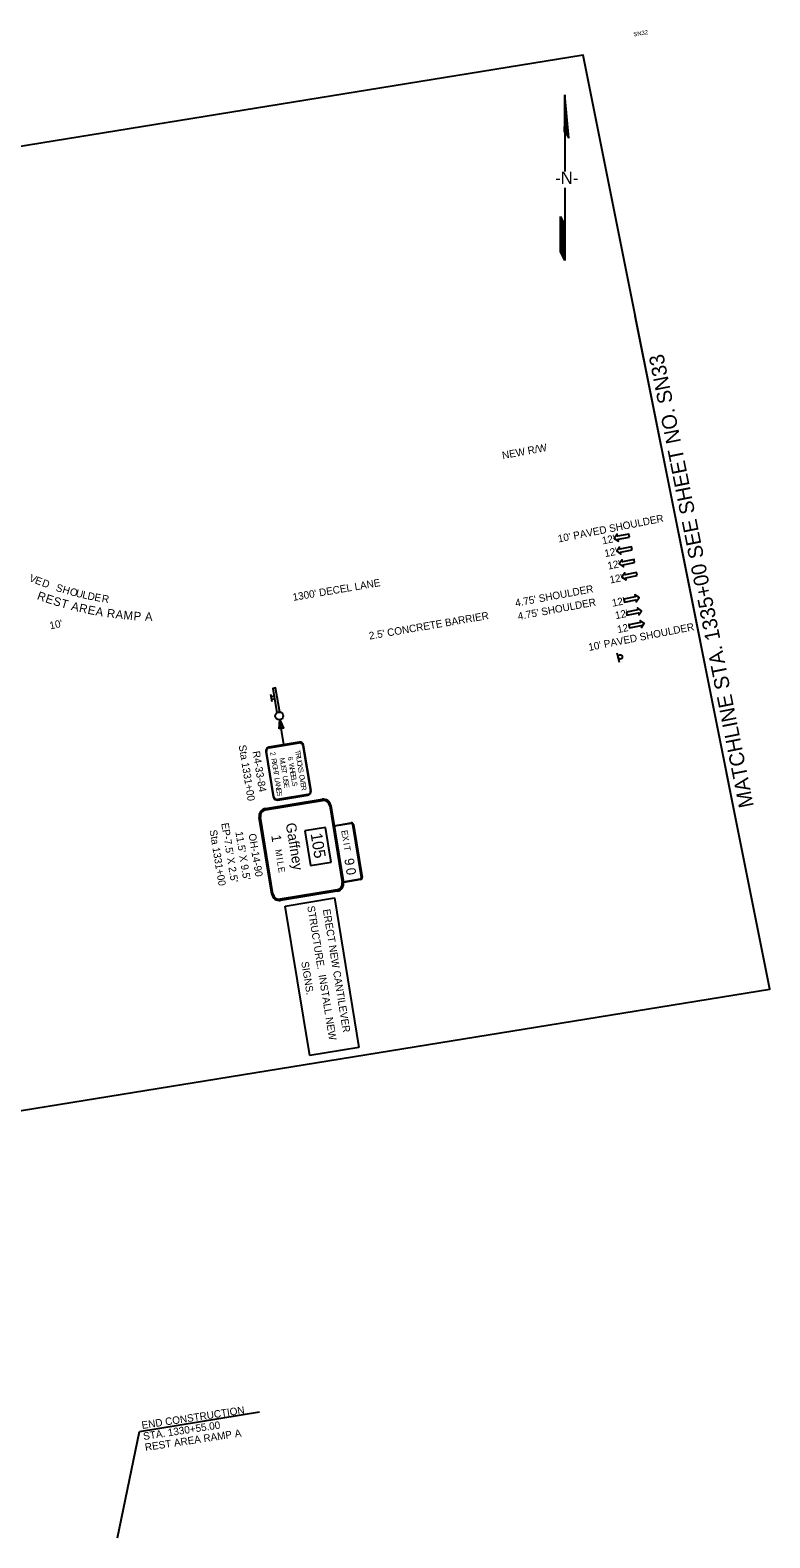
# Model space of a CAD drawing. Extents: x 1781216 to 1782851, y 1180019 to 1181557.
# Drawn here: x 1782155 to 1782851, y 1180139 to 1181557 of the extents above; entities that cross this region are included whole.
import ezdxf

# ---------------------------------------------------------------- set-up
doc = ezdxf.new("R2010")
doc.units = 0
for name, color, linetype in [('RD_HC_Data', 7, 'Continuous'), ('RD_PD_FOC', 7, 'Continuous'), ('RD_PD_GR', 7, 'Continuous'), ('RD_PD_PatLn1', 7, 'Continuous'), ('RD_PD_PaveShd', 7, 'Continuous'), ('RD_SHT_MatchLine', 7, 'Continuous'), ('RD_Sketch1', 7, 'Continuous'), ('RD_Sketch2', 7, 'Continuous'), ('RD_TX_RoadID', 7, 'Continuous')]:
    doc.layers.add(name, color=color, linetype=linetype)

# ---------------------------------------------------------------- blocks, each defined once
blk = doc.blocks.new('NA5')
at = {"layer": 'RD_Sketch1'}
for p, q in [((47.5, 65.9), (26.8, 37.4)), ((26.8, 30.6), (47.5, 65.9)), ((27.2, 37.5), (14.5, 19.8)), ((28.1, 38.3), (26.8, 30.6)), ((14.5, 19.8), (5.5, 7.2)), ((-3.5, -5.3), (-18.5, -26.3)), ((-18.5, -26.3), (-43.3, -60.9)), ((-30.6, -36.2), (-22.3, -24.7)), ((-22.3, -24.7), (-24, -34)), ((-41.6, -51.6), (-30.6, -36.2)), ((-43.3, -60.9), (-41.6, -51.6))]:
    blk.add_line(p, q, dxfattribs=at)
for points in [[(27.4, 37.8), (47.4, 65.8)], [(27.6, 37.9), (46.9, 64.9)], [(27.8, 38.1), (46.4, 64)], [(27.8, 36.8), (42.2, 56.8)], [(27.9, 37.4), (43.8, 59.5)], [(27.9, 37.2), (43.2, 58.6)], [(27.9, 37), (42.7, 57.7)], [(28, 38.1), (45.3, 62.2)], [(28, 37.9), (44.8, 61.3)], [(28, 37.7), (44.3, 60.4)], [(28.1, 38.3), (45.8, 63.1)], [(27.1, 37.6), (39.2, 54.5)], [(27.3, 33.9), (34.8, 44.3)], [(27.3, 33.7), (34.3, 43.4)], [(27.4, 34.5), (36.4, 47)], [(27.4, 34.3), (35.9, 46.1)], [(27.4, 34.1), (35.4, 45.2)], [(27.5, 34.9), (37.5, 48.8)], [(27.5, 34.7), (36.9, 47.9)], [(27.6, 35.5), (39, 51.5)], [(27.6, 35.3), (38.5, 50.6)], [(27.6, 35.1), (38, 49.7)], [(27.7, 36.2), (40.6, 54.2)], [(27.7, 36), (40.1, 53.3)], [(27.7, 35.8), (39.6, 52.4)], [(27.8, 36.6), (41.7, 56)], [(27.8, 36.4), (41.1, 55.1)], [(26.8, 30.7), (27, 30.9)], [(26.9, 37.5), (29.9, 41.7)], [(26.9, 31.3), (28.5, 33.6)], [(26.9, 31.1), (28, 32.7)], [(26.9, 30.9), (27.5, 31.8)], [(27, 32), (30.1, 36.3)], [(27, 31.8), (29.6, 35.4)], [(27, 31.5), (29.1, 34.5)], [(27.1, 32.6), (31.7, 39)], [(27.1, 32.4), (31.2, 38.1)], [(27.1, 32.2), (30.6, 37.2)], [(27.2, 33.2), (33.3, 41.6)], [(27.2, 33), (32.7, 40.7)], [(27.2, 32.8), (32.2, 39.9)], [(27.3, 33.4), (33.8, 42.5)], [(-42.2, -54.8), (-22.9, -27.9)], [(-42.2, -55), (-23, -28.2)], [(-42.1, -54.4), (-22.8, -27.5)], [(-42.1, -54.6), (-22.9, -27.7)], [(-42, -53.7), (-22.7, -26.8)], [(-42, -53.9), (-22.7, -27.1)], [(-42, -54.2), (-22.8, -27.3)], [(-41.9, -53.3), (-22.6, -26.4)], [(-41.9, -53.5), (-22.7, -26.6)], [(-41.8, -52.6), (-22.5, -25.7)], [(-41.8, -52.8), (-22.5, -26)], [(-41.8, -53.1), (-22.6, -26.2)], [(-41.7, -52.2), (-22.4, -25.3)], [(-41.7, -52.4), (-22.5, -25.5)], [(-41.6, -51.7), (-22.3, -24.9)], [(-41.6, -52), (-22.4, -25.1)], [(-43.3, -60.8), (-24, -33.9)], [(-43.2, -60.1), (-23.9, -33.2)], [(-43.2, -60.3), (-23.9, -33.4)], [(-43.2, -60.5), (-24, -33.6)], [(-43.1, -59.7), (-23.8, -32.8)], [(-43.1, -59.9), (-23.9, -33)], [(-43, -59), (-23.7, -32.1)], [(-43, -59.2), (-23.7, -32.3)], [(-43, -59.4), (-23.8, -32.5)], [(-42.9, -58.6), (-23.6, -31.7)], [(-42.9, -58.8), (-23.7, -31.9)], [(-42.8, -58.1), (-23.5, -31.2)], [(-42.8, -58.3), (-23.6, -31.4)], [(-42.7, -57.5), (-23.4, -30.6)], [(-42.7, -57.7), (-23.5, -30.8)], [(-42.7, -57.9), (-23.5, -31)], [(-42.6, -57), (-23.3, -30.1)], [(-42.6, -57.2), (-23.4, -30.4)], [(-42.5, -56.4), (-23.2, -29.5)], [(-42.5, -56.6), (-23.2, -29.7)], [(-42.5, -56.8), (-23.3, -29.9)], [(-42.4, -55.9), (-23.1, -29)], [(-42.4, -56.1), (-23.2, -29.3)], [(-42.3, -55.3), (-23, -28.4)], [(-42.3, -55.5), (-23, -28.6)], [(-42.3, -55.7), (-23.1, -28.8)]]:
    blk.add_lwpolyline(points, dxfattribs=at)
blk.add_text('-N-', height=11.81, rotation=324.3865, dxfattribs=at).set_placement((-8.8, 3))
blk = doc.blocks.new('SARRW2')
at = {"layer": 'RD_Sketch2'}
blk.add_lwpolyline([(-12, 1.2), (-12, -1.2), (-2.8, -1.2), (-2.8, -2.8), (0, 0), (-2.8, 2.8), (-2.8, 1.2)], close=True, dxfattribs=at)

msp = doc.modelspace()

# ---------------------------------------------------------------- linework, layer by layer
at = {"layer": 'RD_HC_Data'}
msp.add_lwpolyline([(1782773.7, 1181039.1), (1782674.9, 1181533), (1782674.9, 1181533), (1781216, 1181296.2), (1781292.5, 1180802), (1781372.6, 1180308.5), (1782060.7, 1180420.2), (1782043.9, 1180523.8), (1782850.5, 1180654.8)], close=True, dxfattribs=at)
at = {"layer": 'RD_PD_GR'}
for p, q in [((1782257.7, 1180238.8), (1782370.5, 1180257.1)), ((1782237, 1180138.6), (1782257.7, 1180238.8))]:
    msp.add_line(p, q, dxfattribs=at)
at = {"layer": 'RD_PD_PatLn1'}
for p, q in [((1782706.7, 1180971), (1782708.9, 1180962.2)), ((1782382.4, 1180925), (1782381.2, 1180931.8)), ((1782384.3, 1180930.2), (1782381.5, 1180929.7)), ((1782384.7, 1180927.5), (1782382, 1180927.1)), ((1782393.6, 1180884.6), (1782389.8, 1180907.9)), ((1782394.9, 1180732.8), (1782441.1, 1180740.4)), ((1782417.9, 1180592.3), (1782394.9, 1180732.8)), ((1782441.1, 1180740.4), (1782464.1, 1180599.8)), ((1782464.1, 1180599.8), (1782417.9, 1180592.3))]:
    msp.add_line(p, q, dxfattribs=at)
for points in [[(1782389.7, 1180915.2), (1782385.7, 1180938), (1782383, 1180937.5), (1782387, 1180914.6)], [(1782376.5, 1180878.1), (1782383.5, 1180835.5)], [(1782384.1, 1180835.6), (1782377.1, 1180878.2)], [(1782407.9, 1180886.9), (1782379.5, 1180882.2)], [(1782379.6, 1180881.6), (1782408, 1180886.3)], [(1782411.5, 1180883.8), (1782418.5, 1180841.2)], [(1782419.1, 1180841.3), (1782412.1, 1180883.9)], [(1782376.2, 1180824.5), (1782429.5, 1180833.2)], [(1782376.4, 1180823.3), (1782429.7, 1180832)], [(1782416, 1180837.8), (1782387.6, 1180833.1)], [(1782387.7, 1180832.5), (1782416.1, 1180837.2)], [(1782436.6, 1180827.1), (1782448.4, 1180754.9)], [(1782437.8, 1180827.3), (1782449.6, 1180755.1)], [(1782382.1, 1180744), (1782370.3, 1180816.2)], [(1782383.3, 1180744.2), (1782371.5, 1180816.4)], [(1782432.6, 1180806.7), (1782413.2, 1180803.5)], [(1782413.2, 1180803.5), (1782418.6, 1180770.9)], [(1782438, 1180774.1), (1782432.6, 1180806.7)], [(1782456.9, 1180810.4), (1782441, 1180807.8), (1782440.9, 1180808.4), (1782456.8, 1180811)], [(1782466.5, 1180759.7), (1782458.3, 1180809.4)], [(1782458.9, 1180809.5), (1782467.1, 1180759.8)], [(1782418.6, 1180770.9), (1782438, 1180774.1)], [(1782443.5, 1180748), (1782390.2, 1180739.3)], [(1782443.7, 1180746.8), (1782390.4, 1180738.1)], [(1782449.5, 1180755.7), (1782465.5, 1180758.3)], [(1782465.6, 1180757.7), (1782449.6, 1180755.1), (1782449.5, 1180755.7)]]:
    msp.add_lwpolyline(points, dxfattribs=at)
msp.add_lwpolyline([(1782389.2, 1180899.5), (1782389.8, 1180907.9), (1782393.3, 1180900.2)], close=True, dxfattribs=at)
for centre, radius in [((1782709.8, 1180967.1), 2), ((1782389.2, 1180911.6), 3.71)]:
    msp.add_circle(centre, radius, dxfattribs=at)
for centre, radius, start, end in [((1782380.1, 1180878.7), 3.6, 99.3129, 189.3129), ((1782380.1, 1180878.7), 3, 99.3129, 189.3129), ((1782408.5, 1180883.4), 3.6, 9.3129, 99.3129), ((1782408.5, 1180883.4), 3, 9.3129, 99.3129), ((1782387.1, 1180836.1), 3.6, 189.3129, 279.3129), ((1782387.1, 1180836.1), 3, 189.3129, 279.3129), ((1782415.5, 1180840.7), 3, 279.3129, 9.3129), ((1782415.5, 1180840.7), 3.6, 279.3129, 9.3129), ((1782430.7, 1180826.1), 7.2, 9.3129, 99.3129), ((1782430.7, 1180826.1), 6, 9.3129, 99.3129), ((1782377.4, 1180817.4), 7.2, 99.3129, 189.3129), ((1782377.4, 1180817.4), 6, 99.3129, 189.3129), ((1782457.1, 1180809.3), 1.8, 9.3129, 99.3129), ((1782457.1, 1180809.3), 1.2, 9.3129, 99.3129), ((1782442.5, 1180754), 6, 279.3129, 9.3129), ((1782442.5, 1180754), 7.2, 279.3129, 9.3129), ((1782465.3, 1180759.5), 1.2, 279.3129, 9.3129), ((1782465.3, 1180759.5), 1.8, 279.3129, 9.3129), ((1782389.2, 1180745.2), 7.2, 189.3129, 279.3129), ((1782389.2, 1180745.2), 6, 189.3129, 279.3129)]:
    msp.add_arc(centre, radius, start, end, dxfattribs=at)
at = {"layer": 'RD_SHT_MatchLine'}
msp.add_lwpolyline([(1782822.1, 1180797.2), (1782773, 1181042.4), (1782724, 1181287.5)], dxfattribs=at)

# ---------------------------------------------------------------- block references
at = {"layer": 'RD_SHT_MatchLine', "rotation": 35.61349782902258}
msp.add_blockref('NA5', (1782657.5, 1181414.5), dxfattribs=at)
at = {"layer": 'RD_Sketch2', "xscale": 1.2}
for p, yscale, rotation in [((1782704.2, 1181078.5), 1.2000000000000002, -168.79893202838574), ((1782706.6, 1181066.5), 1.2000000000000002, -168.79893202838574), ((1782709, 1181054.5), 1.2000000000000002, -168.79893202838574), ((1782711.4, 1181042.2), 1.2000000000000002, -168.79893202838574), ((1782727.6, 1181022.9), 1.2, 11.201067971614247), ((1782730, 1181010.6), 1.2, 11.201067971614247), ((1782732.4, 1180998.7), 1.2, 11.201067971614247)]:
    msp.add_blockref('SARRW2', p, dxfattribs=dict(at, yscale=yscale, rotation=rotation))

# ---------------------------------------------------------------- texts
at = {"layer": 'RD_PD_FOC'}
msp.add_text('NEW R/W', height=7, rotation=10.5494, dxfattribs=at).set_placement((1782599.4, 1181153.1))
at = {"layer": 'RD_PD_GR'}
for s, rotation, p in [("10' PAVED SHOULDER", 11.2011, (1782651.9, 1181074.7)), ("12'", 11.2011, (1782693.4, 1181072.9)), ("12'", 11.2011, (1782695.7, 1181060.9)), ("12'", 11.2011, (1782698.6, 1181049.2)), ('V', 337.6181, (1782153.4, 1181038.7)), ("12'", 11.2011, (1782700.6, 1181036.1)), ('E', 338.6716, (1782158.8, 1181036.5)), ('D', 339.948, (1782165.4, 1181033.9)), ('S', 342.4299, (1782178.5, 1181029.4)), ('H', 343.605, (1782184.7, 1181027.5)), ('O', 344.8814, (1782191.6, 1181025.5)), ('U', 345.9551, (1782197.3, 1181024)), ("1300' DECEL LANE", 9.6289, (1782402.4, 1181019.8)), ("4.75' SHOULDER", 10.5981, (1782611.7, 1181014.3)), ('L', 347.0897, (1782203.5, 1181022.5)), ('D', 348.0014, (1782208.4, 1181021.4)), ('E', 349.1967, (1782214.9, 1181020.1)), ('R', 350.4731, (1782221.9, 1181018.8)), ("4.75' SHOULDER", 10.5981, (1782614.1, 1181001.8)), ("12'", 11.2011, (1782702.8, 1181014.3)), ("10'", 11.7844, (1782173.9, 1180993)), ("2.5' CONCRETE BARRIER", 9.7883, (1782474.2, 1180983.4)), ("12'", 11.2011, (1782705.7, 1181002.6)), ("10' PAVED SHOULDER", 11.2011, (1782680.6, 1180972.7)), ("12'", 11.2011, (1782707.7, 1180989.5)), ('END CONSTRUCTION', 8.5932, (1782260.3, 1180241)), ('STA. 1330+55.00', 8.5932, (1782261.8, 1180230.6)), ('REST AREA RAMP A', 8.5932, (1782263.4, 1180220.3))]:
    msp.add_text(s, height=7, rotation=rotation, dxfattribs=at).set_placement(p)
at = {"layer": 'RD_PD_PatLn1'}
for s, height, rotation, p in [('Sta 1331+00', 7, 279.313, (1782351, 1180883.8)), ('R4-33-84', 7, 279.313, (1782364, 1180878.1)), ('2', 4.8, 279.3129, (1782380.6, 1180877.4)), ('T', 4.8, 279.3129, (1782404, 1180879.3)), ('R', 4.8, 279.3129, (1782404.5, 1180876.2)), ('R', 4.8, 279.3129, (1782381.6, 1180871.3)), ('I', 4.8, 279.3129, (1782382.2, 1180867.7)), ('G', 4.8, 279.3129, (1782382.5, 1180866)), ('H', 4.8, 279.3129, (1782383.1, 1180862.5)), ('T', 4.8, 279.3129, (1782383.6, 1180859.1)), ('M', 4.8, 279.3129, (1782389.4, 1180871.9)), ('U', 4.8, 279.3129, (1782390.1, 1180867.9)), ('S', 4.8, 279.3129, (1782390.7, 1180864.3)), ('T', 4.8, 279.3129, (1782391.2, 1180860.9)), ('6', 4.8, 279.3129, (1782397.1, 1180873)), ('W', 4.8, 279.3129, (1782398.1, 1180866.9)), ('H', 4.8, 279.3129, (1782398.8, 1180862.5)), ('U', 4.8, 279.3129, (1782405.1, 1180872.6)), ('C', 4.8, 279.3129, (1782405.7, 1180869)), ('K', 4.8, 279.3129, (1782406.2, 1180865.6)), ('S', 4.8, 279.3129, (1782406.8, 1180862.2)), ('L', 4.8, 279.3129, (1782384.6, 1180853.1)), ('A', 4.8, 279.3129, (1782385, 1180850.5)), ('N', 4.8, 279.3129, (1782385.6, 1180846.8)), ('U', 4.8, 279.3129, (1782392.2, 1180855)), ('S', 4.8, 279.3129, (1782392.8, 1180851.4)), ('E', 4.8, 279.3129, (1782393.4, 1180847.8)), ('E', 4.8, 279.3129, (1782399.4, 1180859)), ('E', 4.8, 279.3129, (1782400, 1180855.8)), ('L', 4.8, 279.3129, (1782400.5, 1180852.6)), ('S', 4.8, 279.3129, (1782401, 1180849.4)), ('O', 4.8, 279.3129, (1782407.8, 1180856.1)), ('V', 4.8, 279.3129, (1782408.4, 1180852.5)), ('E', 4.8, 279.3129, (1782409, 1180848.8)), ('R', 4.8, 279.3129, (1782409.5, 1180845.7)), ('E', 4.8, 279.3129, (1782386.2, 1180843.2)), ('S', 4.8, 279.3129, (1782386.7, 1180840)), ('Sta 1331+00', 7, 279.313, (1782323.6, 1180804)), ("EP-7.5' X 2.5'", 7, 279.313, (1782334.6, 1180810.5)), ('Gaffney', 9.6, 279.3129, (1782395.2, 1180810.3)), ('E', 6, 279.3129, (1782447.4, 1180803.7)), ("11.5' X 9.5'", 7, 279.313, (1782347.9, 1180802.4)), ('OH-14-90', 7, 279.313, (1782360.3, 1180800.5)), ('1', 9, 279.3129, (1782381.6, 1180799.1)), ('105', 10.8, 279.3129, (1782418.6, 1180800.8)), ('X', 6, 279.3129, (1782448.2, 1180798.6)), ('I', 6, 279.3129, (1782449.4, 1180791.9)), ('T', 6, 279.3129, (1782449.8, 1180788.9)), ('M', 6, 279.3129, (1782385.3, 1180785.7)), ('I', 6, 279.3129, (1782386.6, 1180778)), ('L', 6, 279.3129, (1782387.1, 1180774.4)), ('9', 9, 279.3129, (1782450.3, 1180777)), ('E', 6, 279.3129, (1782388, 1180769.1)), ('0', 9, 279.3129, (1782451.7, 1180768)), ('STRUCTURE.  INSTALL NEW', 7, 279.313, (1782415.5, 1180732.5)), ('ERECT NEW CANTILEVER', 7, 279.313, (1782430.2, 1180729.4)), ('SIGNS.', 7, 279.313, (1782409.8, 1180680.2))]:
    msp.add_text(s, height=height, rotation=rotation, dxfattribs=at).set_placement(p)
at = {"layer": 'RD_PD_PaveShd'}
msp.add_text('SN32', height=4, rotation=9.22, dxfattribs=at).set_placement((1782722.6, 1181550.6))
at = {"layer": 'RD_SHT_MatchLine'}
msp.add_text('MATCHLINE STA. 1335+00 SEE SHEET NO. SN33', height=14, rotation=101.3102, dxfattribs=at).set_placement((1782835.5, 1180826.8))
at = {"layer": 'RD_TX_RoadID'}
for s, rotation, p in [('R', 340.3914, (1782160.8, 1181021.5)), ('E', 341.819, (1782168.6, 1181018.7)), ('S', 343.1377, (1782175.9, 1181016.3)), ('T', 344.4565, (1782183.2, 1181014.1)), ('A', 346.213, (1782193, 1181011.4)), ('R', 347.5318, (1782200.4, 1181009.6)), ('E', 348.9594, (1782208.5, 1181007.8)), ('A', 350.2782, (1782216, 1181006.3)), ('R', 352.1457, (1782226.7, 1181004.6)), ('A', 353.5734, (1782234.9, 1181003.4)), ('M', 354.8921, (1782242.4, 1181002.6)), ('P', 356.5387, (1782252, 1181001.7)), ('A', 358.4063, (1782262.8, 1181001.1))]:
    msp.add_text(s, height=8, rotation=rotation, dxfattribs=at).set_placement(p)

doc.saveas('drawing.dxf')
